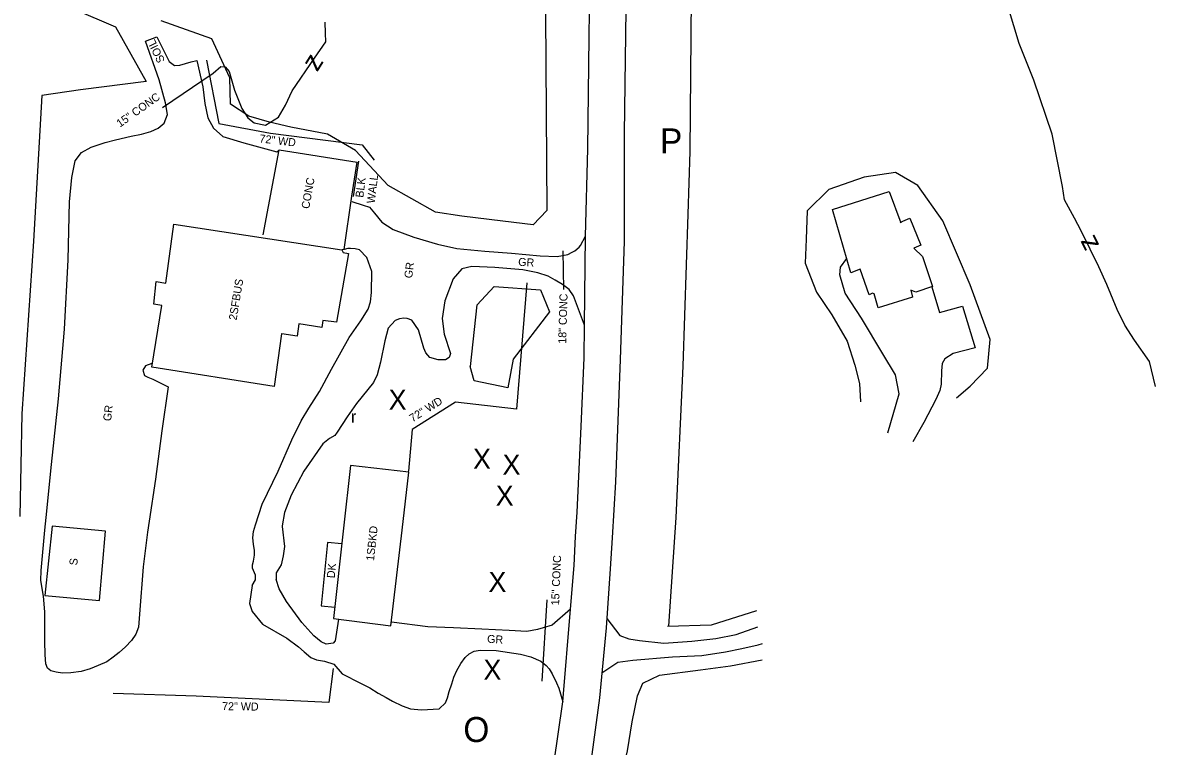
# Model space of a CAD drawing. Extents: x 2030130 to 2036320, y 723205 to 762423.
# Drawn here: x 2032243 to 2032809, y 748955 to 749317 of the extents above; entities that cross this region are included whole.
import ezdxf

# ---------------------------------------------------------------- set-up
doc = ezdxf.new("R2010")
doc.units = 0
for name, color, linetype in [('Draft_Bearing Label', 7, 'Continuous'), ('Draft_Station Cardinal Points', 7, 'Continuous'), ('Draft_Station Labels Major', 7, 'Continuous'), ('Draft_Station Tics Major', 7, 'Continuous'), ('Draft_Station Tics Minor', 7, 'Continuous'), ('Exist Terrain Model Ground Surface', 7, 'Continuous'), ('Old_Level_23', 7, 'Continuous'), ('Old_Level_26', 7, 'Continuous'), ('Old_Level_28', 7, 'Continuous'), ('Prop Alignment Horizontal', 7, 'Continuous'), ('Prop Horizontal Alignment Ramp', 7, 'Continuous')]:
    doc.layers.add(name, color=color, linetype=linetype)

msp = doc.modelspace()

# ---------------------------------------------------------------- linework, layer by layer
at = {"layer": 'Draft_Station Labels Major'}
for p, q in [((2032407.48, 749230.15), (2032410.2, 749247.14)), ((2032403.78, 749203.48), (2032407.48, 749230.14))]:
    msp.add_line(p, q, dxfattribs=at)
for points in [[(2032543.36, 749792.2), (2032543.52, 749726.54), (2032543.7, 749688.57), (2032544.71, 749648.99), (2032544.69, 749614.41), (2032544.87, 749567.25), (2032545.13, 749501.3), (2032544.37, 749443.26), (2032544.46, 749399), (2032544.63, 749335.85), (2032543.7, 749261.25), (2032543.69, 749207.39), (2032541.71, 749148.35), (2032539.4, 749087.26), (2032537.63, 749059.25)], [(2032519.41, 749059.91), (2032520.1, 749072.05), (2032522.09, 749114.92), (2032523.58, 749149.24), (2032523.86, 749165.53), (2032524.35, 749210.1), (2032525.45, 749253.72), (2032526.08, 749309.53), (2032526.63, 749348.67), (2032526.73, 749380.54), (2032526.59, 749410.76), (2032526.55, 749446.98), (2032527.11, 749489.22), (2032526.92, 749543.17), (2032527.13, 749606.52), (2032526.75, 749657.26), (2032526, 749714.77)], [(2032254.79, 749069.45), (2032257.41, 749095.99), (2032260.86, 749128.7), (2032263.94, 749163.62), (2032265.69, 749198.3), (2032266.45, 749227.27), (2032267.62, 749239.46), (2032269.3, 749247.8), (2032272.45, 749251.95), (2032277.19, 749254.6), (2032284.17, 749256.84), (2032289.43, 749258.25), (2032297.29, 749260.04), (2032302.46, 749261.06), (2032307.15, 749262.46), (2032310.67, 749264.11), (2032313.68, 749266.61), (2032315.38, 749270.91), (2032314.43, 749276.67), (2032311.29, 749288.24), (2032304.33, 749307.62), (2032310.15, 749309.82), (2032316.22, 749297.37), (2032318.88, 749295.42), (2032321.58, 749295.6), (2032324.35, 749296.36), (2032327.22, 749297.31), (2032329.99, 749297.98), (2032333, 749284.76), (2032334.12, 749276.4), (2032335.5, 749269.2), (2032338.35, 749264.08), (2032343.01, 749259.98), (2032353.53, 749256.73), (2032370.07, 749252.21), (2032370.96, 749252.86)], [(2032363.18, 749210.69), (2032371.24, 749253.29), (2032410.2, 749247.14)], [(2032407.48, 749227.42), (2032413.23, 749225.55), (2032416.34, 749224.58), (2032418.85, 749221.57), (2032422.46, 749217.05), (2032428.26, 749213.37), (2032438.51, 749209.53), (2032450.28, 749206.03), (2032460.09, 749203.92), (2032473.93, 749202.51), (2032487.37, 749201.56), (2032501.59, 749200.26), (2032510.19, 749199.84), (2032515.56, 749200.88), (2032517.64, 749202), (2032518.97, 749202.81), (2032521.14, 749204.52), (2032521.88, 749205.41), (2032524.35, 749210.1)], [(2032359.47, 749065.68), (2032362.68, 749076.13), (2032370.67, 749092.58), (2032377.62, 749108.23), (2032382.16, 749117.82), (2032386.11, 749124.11), (2032391.36, 749132.37), (2032397.39, 749143.65), (2032406.17, 749159.45), (2032411.99, 749167.73), (2032415.67, 749173.63), (2032416.82, 749177.23), (2032417.45, 749181.88), (2032417.61, 749192.4), (2032415.08, 749199.37), (2032411.3, 749203.3), (2032409.16, 749203.82), (2032406.84, 749203.94), (2032405.49, 749203.9), (2032403.78, 749203.48)], [(2032403.78, 749203.48), (2032402.64, 749203.2)], [(2032675.52, 749111.75), (2032681.1, 749131.2), (2032679.27, 749140.79), (2032672.97, 749151.2), (2032662.21, 749169.12), (2032654.12, 749181.6), (2032651.53, 749190.77), (2032651.8, 749194.63), (2032654.9, 749198.88)], [(2032523.86, 749165.53), (2032518.4, 749180.22), (2032516.09, 749183.43), (2032512.83, 749185.84), (2032509.1, 749188.04), (2032505.66, 749190.06), (2032500.5, 749191.74), (2032492.93, 749193.24), (2032479, 749194.36), (2032467.5, 749194.88), (2032462.52, 749193.77), (2032458.24, 749188.72), (2032453.94, 749177.78), (2032452.67, 749168.87), (2032453.67, 749161.08), (2032456.86, 749151.44), (2032456.15, 749149.49), (2032454.35, 749148.27), (2032450.69, 749148.26), (2032446.5, 749149.48), (2032444.5, 749151.74), (2032443.57, 749154.02), (2032440.87, 749163.3), (2032437.55, 749168.02), (2032435.2, 749168.92), (2032433.46, 749169.06), (2032431.35, 749168.8), (2032429.16, 749167.86), (2032425.7, 749164.09), (2032423.97, 749157.67), (2032421.88, 749147), (2032420.24, 749140.68), (2032418.43, 749136.96), (2032409.87, 749126.38), (2032405.15, 749119.77), (2032400.28, 749112), (2032398.97, 749110.42), (2032396.32, 749108.89), (2032393.02, 749106.28), (2032383.6, 749092.59), (2032377.21, 749080.62), (2032373.81, 749071.93), (2032372.71, 749065.2)], [(2032697.39, 749184.73), (2032701.26, 749171.85), (2032712.73, 749175.09), (2032719.15, 749154.27), (2032708.05, 749151.42), (2032703.89, 749148.79), (2032702.61, 749146.44), (2032702.34, 749142.77), (2032702.16, 749136.01), (2032701.48, 749132.91), (2032699.5, 749128.41), (2032693.49, 749116.86), (2032688, 749107.24)], [(2032307.73, 749146.4), (2032307.59, 749146.42), (2032304.34, 749145.17), (2032303.06, 749143), (2032303.91, 749140.43), (2032305.58, 749139.51), (2032308.12, 749138.53), (2032315.75, 749134.8), (2032312.56, 749112.71), (2032309.34, 749088.59), (2032306.24, 749067.6)], [(2032252.27, 749042.97), (2032254.17, 749063.09), (2032254.79, 749069.45)], [(2032306.24, 749067.6), (2032305.42, 749062.04), (2032303.25, 749044.71)], [(2032357.65, 749035.46), (2032359.39, 749038.31), (2032359.42, 749040.53), (2032357.96, 749044.06), (2032357.82, 749045.79), (2032358.34, 749047.54), (2032358.92, 749050.65), (2032358.85, 749052.96), (2032358.37, 749056.13), (2032357.98, 749059.3), (2032358.47, 749062.4), (2032359.47, 749065.68)], [(2032372.71, 749065.2), (2032372.67, 749064.95), (2032373.84, 749054.96), (2032373.21, 749050.31), (2032372.19, 749045.74), (2032369.71, 749041.71), (2032369.71, 749038.34)], [(2032518.59, 749045.37), (2032519.41, 749059.91)], [(2032537.63, 749059.25), (2032536.65, 749043.69)], [(2032303.25, 749044.71), (2032301.4, 749021.04), (2032300.93, 749014.61), (2032299.53, 749011.13), (2032297.39, 749007.9), (2032294.47, 749004.72), (2032291.18, 749001.96), (2032288.21, 748999.56), (2032285.03, 748997.21), (2032280.68, 748995.42), (2032276.7, 748993.71), (2032272.26, 748992.4), (2032267.11, 748991.73), (2032262.95, 748991.55), (2032259.74, 748992.02), (2032257.15, 748992.81), (2032255.46, 748994.06), (2032254.66, 748996.25), (2032254.21, 749000.76), (2032254.12, 749007.57), (2032254.11, 749022.31), (2032253.35, 749030.08), (2032252.11, 749037.85), (2032252.27, 749042.97)], [(2032436.77, 748486.29), (2032437.78, 748501.85), (2032441.5, 748542.7), (2032443.53, 748563.74), (2032450.82, 748616.35), (2032459.27, 748668.99), (2032468.06, 748716.13), (2032476.1, 748761.48), (2032486.5, 748813.61), (2032497.51, 748872.95), (2032502.61, 748904.8), (2032508.48, 748946.14), (2032512.94, 748977.18), (2032516.91, 749023.52), (2032518.59, 749045.37)], [(2032536.65, 749043.69), (2032534.71, 749014.28), (2032531.27, 748979.24), (2032526.16, 748941.16), (2032520.46, 748901.02), (2032514.09, 748861.34), (2032504.08, 748810.76), (2032500.64, 748791.02), (2032495.22, 748763.5), (2032489.75, 748730.52), (2032480.21, 748679.53), (2032470.5, 748624.78), (2032468.27, 748610.04), (2032464.18, 748580.63), (2032460.61, 748554.72), (2032458.08, 748529.5), (2032455.9, 748501.32), (2032455.45, 748490.23)], [(2032400.87, 749018.55), (2032399.13, 749007.76), (2032398.27, 749006.63), (2032394.68, 749006.15), (2032392.25, 749007.25), (2032388.48, 749010.33), (2032382.59, 749016.99), (2032374.93, 749027.48), (2032371.24, 749033.77), (2032369.71, 749038.34)], [(2032357.65, 749035.46), (2032356.42, 749026.42), (2032357.64, 749022.48), (2032362.89, 749016.09), (2032375.12, 749009.16), (2032380.87, 749004.8), (2032383.68, 749002.22), (2032387.1, 748999.47), (2032389.94, 748998.25), (2032393.85, 748997.52), (2032398.56, 748996.17), (2032402.77, 748991.24), (2032411.95, 748986.65), (2032416.55, 748984.3), (2032420.74, 748981.59), (2032424.63, 748979.41), (2032427.78, 748977.57), (2032432.66, 748975.28), (2032436.81, 748973.82), (2032442.35, 748973.2), (2032451.16, 748973.77), (2032454.28, 748976.78), (2032455.38, 748979.21), (2032456.24, 748982.37), (2032457.55, 748986.3), (2032458.58, 748989.59), (2032460.01, 748992.86), (2032462.06, 748996.43), (2032464.12, 748999.43), (2032466.11, 749001.25), (2032468.68, 749002.51), (2032471.68, 749003.06), (2032479.65, 749002.9), (2032491.81, 749001.09), (2032496.99, 748999.82), (2032502.04, 748997.66), (2032504.68, 748995.44), (2032506.24, 748993.79), (2032507.59, 748991.23), (2032509.77, 748986.79), (2032510.95, 748984.1), (2032512.94, 748977.18)], [(2032516.91, 749023.52), (2032507.74, 749015.52), (2032503.14, 749014.19), (2032500.27, 749013.46), (2032494.94, 749012.47), (2032486.13, 749012.96), (2032472.44, 749013.62), (2032458.36, 749014.3), (2032445.5, 749014.72), (2032427.28, 749017.13)], [(2032535.01, 749018.91), (2032541.55, 749010.49), (2032546.07, 749008.7), (2032551.38, 749007.93), (2032563.43, 749006.56), (2032577.46, 749007.6), (2032589.41, 749008.85), (2032599.67, 749010.85), (2032610.53, 749014.82)], [(2032532.5, 748991.75), (2032540.47, 748997.13), (2032548, 748998.04), (2032567.75, 748999.76), (2032582.53, 749000.46), (2032594.38, 749002.27), (2032602.47, 749003.87), (2032610.7, 749005.69), (2032612.8, 749006.47)]]:
    msp.add_lwpolyline(points, dxfattribs=at)
at = {"layer": 'Draft_Station Tics Major'}
msp.add_line((2032576.67, 749252.46), (2032579.96, 749619.79), dxfattribs=at)
for points in [[(2032268.82, 749323.58), (2032289.33, 749314.76), (2032304.82, 749287.46), (2032271.97, 749283.18), (2032252.57, 749280.47), (2032248.42, 749207.64), (2032242.56, 749121.25), (2032241.61, 749069.93)], [(2032504.37, 749321.1), (2032505.04, 749222.95), (2032498.12, 749215.8), (2032483.02, 749217.65), (2032462.5, 749220.12), (2032449.33, 749222.03), (2032425.78, 749235.39), (2032409.44, 749252.83), (2032395.3, 749261.08), (2032377.07, 749264.58), (2032366.38, 749267.15), (2032356.07, 749270.11), (2032346.83, 749276), (2032346.51, 749289.23), (2032337.51, 749308.79), (2032312.19, 749317.77)], [(2032565.97, 749015.05), (2032569.58, 749069.44), (2032573.18, 749145.09), (2032575.71, 749221.1), (2032576.67, 749252.46)], [(2032709.8, 749129.24), (2032716.61, 749135.12), (2032725.19, 749144.1), (2032726.6, 749158.4), (2032716.53, 749185.69), (2032702.88, 749217.76), (2032690.46, 749235.47), (2032679.31, 749241.87), (2032663.66, 749239.54), (2032646.01, 749233.46), (2032635.11, 749222.7), (2032634.63, 749208.56), (2032634.07, 749196.66), (2032639.79, 749182.04), (2032647.53, 749170.79), (2032655.06, 749157.55), (2032658.99, 749145.65), (2032661.25, 749136.48), (2032661.79, 749127.25)], [(2032466.91, 749144.84), (2032470.21, 749175.8), (2032478.61, 749184.93), (2032501.81, 749183.32), (2032506.38, 749172.27), (2032488.2, 749148.57), (2032485.55, 749134.22), (2032468.67, 749137.76), (2032466.72, 749144.84)], [(2032609.8, 749022.75), (2032587.12, 749015.66), (2032565.25, 749014.98)], [(2032609.4, 748894.64), (2032570.49, 748896.44), (2032552.52, 748901.16), (2032544.18, 748905.76), (2032539.4, 748916), (2032540.64, 748933.12), (2032545.24, 748952.79), (2032547.73, 748967.27), (2032550.32, 748980.23), (2032552.96, 748986.67), (2032561.27, 748990.51), (2032581.89, 748993.19), (2032596.87, 748995.2), (2032612.61, 748998.32)]]:
    msp.add_lwpolyline(points, dxfattribs=at)
at = {"layer": 'Draft_Station Tics Minor'}
msp.add_line((2032312.89, 749274.38), (2032338.22, 749291.55), dxfattribs=at)
for points in [[(2032513.51, 749183.33), (2032513.11, 749202.71)], [(2032505.05, 749028.27), (2032502.46, 748987.64)]]:
    msp.add_lwpolyline(points, dxfattribs=at)
at = {"layer": 'Exist Terrain Model Ground Surface'}
msp.add_line((2032408.32, 749229.87), (2032411.08, 749247.59), dxfattribs=at)
for points in [[(2032334.85, 749298.02), (2032341.04, 749266.43), (2032366.95, 749261.6), (2032412.65, 749255.73), (2032418.7, 749248.07)], [(2032495.04, 749186.75), (2032489.79, 749123.54), (2032459.37, 749127.07), (2032437.7, 749113.43), (2032435.92, 749092.56)], [(2032432.66, 749063.04), (2032436.06, 749092.07), (2032406.81, 749095.44), (2032403.36, 749064.09)], [(2032403.36, 749064.09), (2032398.38, 749018.86), (2032427.06, 749015.28), (2032432.66, 749063.04)], [(2032402.5, 749056.33), (2032395.35, 749056.95), (2032392.13, 749025.26), (2032399.01, 749024.54)], [(2032398.25, 748993.84), (2032395.96, 748976.95), (2032329.71, 748980.05), (2032288.29, 748981.37)]]:
    msp.add_lwpolyline(points, dxfattribs=at)
for points in [[(2032676.11, 749232.44), (2032681.99, 749216.8), (2032681.69, 749217.08), (2032686.45, 749219.05), (2032691.88, 749205.52), (2032688.45, 749204.07), (2032692.72, 749199.95), (2032697.81, 749184.86), (2032689.41, 749182.1), (2032686.96, 749183.09), (2032687.84, 749179.54), (2032670.64, 749174.2), (2032668.69, 749181.28), (2032667.81, 749181.54), (2032666.1, 749180.81), (2032661.66, 749193.51), (2032656.99, 749191.73), (2032647.73, 749223.38)], [(2032318.59, 749216.06), (2032402.56, 749203.21), (2032403.28, 749201.87), (2032405.91, 749201.47), (2032399.79, 749167), (2032393.08, 749167.95), (2032393.08, 749167.95), (2032392.6, 749164.45), (2032381.12, 749166.33), (2032380.15, 749160.01), (2032372.55, 749161.23), (2032372.46, 749161.32), (2032368.8, 749134.96), (2032307.58, 749144.63), (2032312.56, 749175.39), (2032308.57, 749176.04), (2032309.77, 749187.41), (2032314.64, 749186.59), (2032314.64, 749186.59)], [(2032254.12, 749030.44), (2032281.34, 749027.84), (2032284.49, 749062.52), (2032257.77, 749065.02)]]:
    msp.add_lwpolyline(points, close=True, dxfattribs=at)
at = {"layer": 'Prop Alignment Horizontal'}
for points in [[(2032809.15, 749134.96), (2032806.27, 749147.39), (2032798.73, 749158.04), (2032793.88, 749165.59), (2032790.07, 749173.47), (2032784.98, 749185.83), (2032780.95, 749194.75), (2032776.64, 749203.58), (2032772.13, 749212.78), (2032768.66, 749219.12), (2032763.76, 749228.31), (2032762.79, 749234.83), (2032757.66, 749261.15), (2032748.37, 749288.11), (2032741.07, 749306.47), (2032735.73, 749324.03)], [(2032338.22, 749291.55), (2032341.98, 749294.85), (2032344.2, 749294.72), (2032346.2, 749292.37), (2032347.59, 749287.79), (2032348.9, 749283), (2032352.55, 749273.95), (2032355.58, 749269.31), (2032358.65, 749266.8), (2032364.38, 749265.53), (2032370.82, 749269.58), (2032374.3, 749275.57), (2032377.75, 749282.72), (2032388.83, 749299.07), (2032394.56, 749307.25), (2032394.33, 749311.59), (2032394.17, 749317.08)]]:
    msp.add_lwpolyline(points, dxfattribs=at)

# ---------------------------------------------------------------- texts
at = {"layer": 'Draft_Bearing Label'}
msp.add_text('r', height=6, dxfattribs=at).set_placement((2032407.11, 749116.87))
at = {"layer": 'Draft_Station Cardinal Points'}
msp.add_text('O', height=12.5, dxfattribs=at).set_placement((2032463.27, 748957.16))
at = {"layer": 'Draft_Station Tics Major'}
for p in [(2032425.96, 749123.32), (2032468.13, 749093.75), (2032482.87, 749090.91), (2032479.49, 749075.38), (2032475.85, 749032.22), (2032473.34, 748988.35)]:
    msp.add_text('X', height=10, dxfattribs=at).set_placement(p)
at = {"layer": 'Old_Level_23'}
for s, rotation, p in [('SOIL', 115.8823, (2032314.23, 749297.88)), ('CONC', 79.8697, (2032386.2, 749223.49)), ('GR', 83.085, (2032437.68, 749188.86)), ('GR', 356.4985, (2032490.59, 749195.31)), ('GR', 83.085, (2032287.15, 749117.42)), ('GR', 356.4985, (2032475.06, 749006.8))]:
    msp.add_text(s, height=4, rotation=rotation, dxfattribs=at).set_placement(p)
at = {"layer": 'Old_Level_26'}
for s, rotation, p in [('15" CONC', 35.3651, (2032291.66, 749264.32)), ('18" CONC', 88.352, (2032514.65, 749156.24)), ('15" CONC', 87.5791, (2032511.1, 749025.43))]:
    msp.add_text(s, height=4, rotation=rotation, dxfattribs=at).set_placement(p)
at = {"layer": 'Old_Level_28'}
for s, rotation, p in [('72" WD', 353.1602, (2032361.18, 749257.02)), ('BLK', 82.929, (2032413.25, 749229.17)), ('WALL', 82.929, (2032418.93, 749226.25)), ('2SFBUS', 80.6188, (2032349.92, 749167.84)), ('72" WD', 32.206, (2032437.86, 749116.93)), ('1SBKD', 83.7647, (2032418.6, 749047.56)), ('S', 85.7084, (2032270.31, 749045.39)), ('DK', 84.7611, (2032398.97, 749038.93)), ('72" WD', 359.2424, (2032342.69, 748973.11))]:
    msp.add_text(s, height=4, rotation=rotation, dxfattribs=at).set_placement(p)
at = {"layer": 'Prop Alignment Horizontal'}
for rotation, p in [(58.061, (2032390.22, 749291.88)), (116.7862, (2032781.32, 749205.53))]:
    msp.add_text('z', height=10, rotation=rotation, dxfattribs=at).set_placement(p)
at = {"layer": 'Prop Horizontal Alignment Ramp'}
msp.add_text('P', height=12.5, dxfattribs=at).set_placement((2032561.56, 749251.44))

doc.saveas('drawing.dxf')
